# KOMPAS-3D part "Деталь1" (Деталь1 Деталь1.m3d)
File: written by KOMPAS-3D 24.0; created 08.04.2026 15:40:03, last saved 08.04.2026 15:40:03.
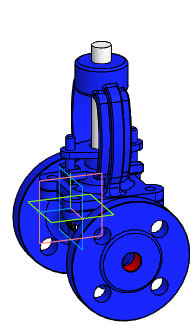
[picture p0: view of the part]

Document properties: Автор: R2D2; Полное имя файла: E:\Работа\Зайцев\VSO1121M-F-S Клапан запорный сальниковый DN.ru\DN15\исходные материалы\Деталь1 Деталь1.m3d

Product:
- Body: Твердое тело1  | qty 1
- Part/product: Деталь1
    additional columns: Типовые

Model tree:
1. Твердое тело1  (labels: Твердое тело1)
